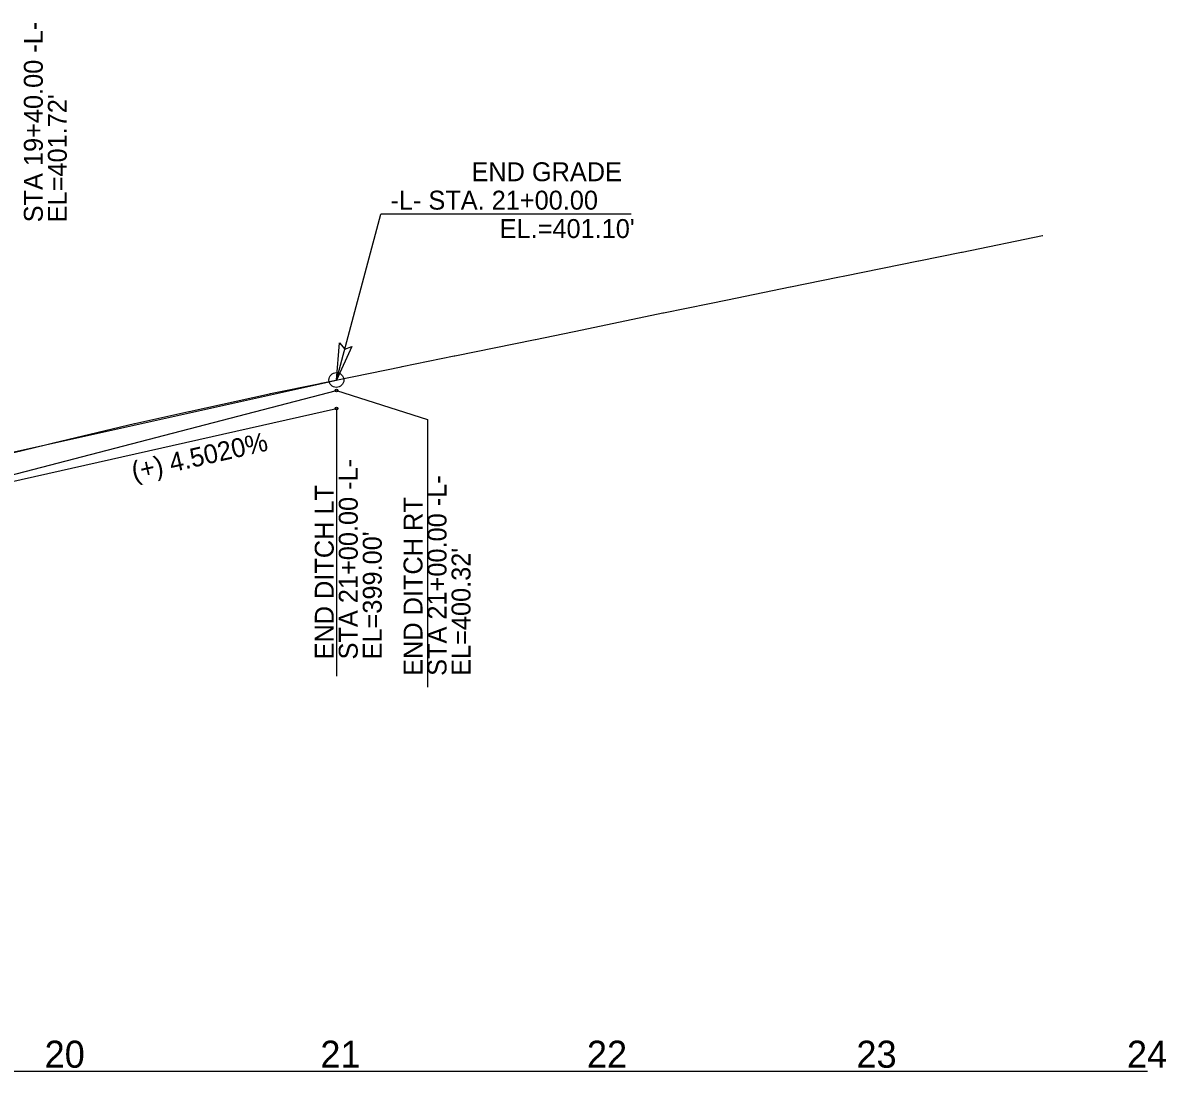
# Model space of a CAD drawing. Extents: x 2099451 to 2100919, y 990328 to 992828.
# Drawn here: x 2100496.2 to 2100919, y 991578.3 to 991965.9 of the extents above; entities that cross this region are included whole.
import ezdxf

# ---------------------------------------------------------------- set-up
doc = ezdxf.new("R2010")
doc.units = 0
for name, color, linetype in [('Exist Profile Cell', 7, 'Continuous'), ('Exist Vertical Profile Ground Line', 7, 'Continuous'), ('Exist Vertical Profile Horizontal Axis Label Major', 7, 'Continuous'), ('Prop Terminator CELL', 7, 'Continuous'), ('Prop Vertical Profile Ditch Grade Left', 7, 'Continuous'), ('Prop Vertical Profile Ditch Grade Left Label', 7, 'Continuous'), ('Prop Vertical Profile Ditch Grade Right', 7, 'Continuous'), ('Prop Vertical Profile Grade', 7, 'Continuous'), ('Prop VPI Ditch Grade Left Label', 7, 'Continuous'), ('Prop VPI Ditch Grade Right Label', 7, 'Continuous'), ('Prop VPI Label', 7, 'Continuous')]:
    doc.layers.add(name, color=color, linetype=linetype)

msp = doc.modelspace()

# ---------------------------------------------------------------- linework, layer by layer
at = {"layer": 'Exist Profile Cell'}
msp.add_line((2099512.14, 991578.31), (2100912.14, 991578.31), dxfattribs=at)
at = {"layer": 'Exist Vertical Profile Ground Line'}
msp.add_lwpolyline([(2100488.78, 991806.06), (2100504.54, 991809.85), (2100507.56, 991810.57), (2100537.46, 991817.74), (2100537.61, 991817.77), (2100557.59, 991822.16), (2100557.73, 991822.19), (2100587.43, 991828.71), (2100587.76, 991828.78), (2100606.19, 991832.58), (2100606.45, 991832.63), (2100636.07, 991838.74), (2100636.44, 991838.82), (2100655.74, 991842.72), (2100655.91, 991842.75), (2100685.68, 991848.77), (2100685.78, 991848.79), (2100703, 991852.39), (2100703.09, 991852.41), (2100732.92, 991858.65), (2100733.09, 991858.68), (2100750.11, 991862.15), (2100750.14, 991862.16), (2100756.76, 991863.51), (2100779.93, 991868.21), (2100780.05, 991868.23), (2100797.6, 991871.8), (2100797.62, 991871.81), (2100800.18, 991872.33), (2100827.42, 991877.84), (2100827.57, 991877.88), (2100843.28, 991881.08), (2100843.51, 991881.13), (2100873.25, 991887.19), (2100873.4, 991887.22)], dxfattribs=at)
at = {"layer": 'Prop Terminator CELL'}
msp.add_lwpolyline([(2100617.88, 991846.25), (2100612.14, 991833.81), (2100613.33, 991847.54), (2100615.21, 991845.25)], close=True, dxfattribs=at)
at = {"layer": 'Prop Vertical Profile Ditch Grade Left'}
msp.add_line((2100367.14, 991768.16), (2100612.14, 991823.31), dxfattribs=at)
at = {"layer": 'Prop Vertical Profile Ditch Grade Left Label'}
msp.add_line((2100612.14, 991823.31), (2100612.14, 991724.32), dxfattribs=at)
at = {"layer": 'Prop Vertical Profile Ditch Grade Right'}
msp.add_lwpolyline([(2100212.14, 991744.91), (2100412.14, 991777.91), (2100612.14, 991829.91)], dxfattribs=at)
at = {"layer": 'Prop Vertical Profile Grade'}
msp.add_line((2100477.14, 991803.81), (2100612.14, 991833.81), dxfattribs=at)
at = {"layer": 'Prop VPI Ditch Grade Left Label'}
msp.add_circle((2100612.14, 991823.31), 0.5, dxfattribs=at)
at = {"layer": 'Prop VPI Ditch Grade Right Label'}
for p, q in [((2100612.14, 991829.91), (2100645.78, 991819.19)), ((2100645.78, 991819.19), (2100645.78, 991720.21))]:
    msp.add_line(p, q, dxfattribs=at)
msp.add_circle((2100612.14, 991829.91), 0.5, dxfattribs=at)
at = {"layer": 'Prop VPI Label'}
for p in [(2100612.14, 991833.81), (2100721.18, 991895.08)]:
    msp.add_line(p, (2100628.54, 991895.08), dxfattribs=at)
msp.add_circle((2100612.14, 991833.81), 2.75, dxfattribs=at)

# ---------------------------------------------------------------- texts
at = {"layer": 'Exist Vertical Profile Horizontal Axis Label Major'}
for s, p in [('20', (2100504.23, 991579.56)), ('21', (2100606.21, 991579.56)), ('22', (2100704.78, 991579.56)), ('23', (2100804.45, 991579.56)), ('24', (2100904.51, 991579.56))]:
    msp.add_text(s, height=10, dxfattribs=at).set_placement(p)
at = {"layer": 'Prop Vertical Profile Ditch Grade Left Label'}
msp.add_text('(+) 4.5020%', height=7, rotation=12.6859, dxfattribs=at).set_placement((2100537.26, 991796.55))
at = {"layer": 'Prop VPI Ditch Grade Left Label'}
for s, p in [('STA 21+00.00 -L-', (2100620.03, 991730.51)), ('END DITCH LT', (2100611.15, 991730.51)), ("EL=399.00'", (2100628.9, 991730.51))]:
    msp.add_text(s, height=7, rotation=90, dxfattribs=at).set_placement(p)
at = {"layer": 'Prop VPI Ditch Grade Right Label'}
for s, p in [('STA 19+40.00 -L-', (2100503.57, 991892.12)), ("EL=401.72'", (2100512.44, 991892.12)), ('STA 21+00.00 -L-', (2100652.87, 991724.44)), ('END DITCH RT', (2100643.99, 991724.44)), ("EL=400.32'", (2100661.74, 991724.44))]:
    msp.add_text(s, height=7, rotation=90, dxfattribs=at).set_placement(p)
at = {"layer": 'Prop VPI Label'}
for s, p in [('END GRADE', (2100662.09, 991907.31)), ('-L- STA. 21+00.00', (2100632.13, 991896.81)), ("EL.=401.10'", (2100672.52, 991886.31))]:
    msp.add_text(s, height=7, dxfattribs=at).set_placement(p)

doc.saveas('drawing.dxf')
